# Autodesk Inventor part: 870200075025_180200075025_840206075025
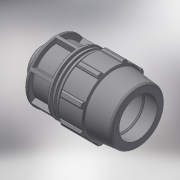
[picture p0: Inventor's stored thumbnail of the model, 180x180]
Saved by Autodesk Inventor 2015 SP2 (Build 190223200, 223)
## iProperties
Created: 2017-02
Part Number: 870200075025_180200075025_840206075025
Material: Generic
Description: PLASSON MALE ADAPTOR 75-2.1/2"
Document SubType Name: Modeling
Designer: KIM
Mass: 964.158 g
Surface Area: 1468.9 cm^2
Volume: 964.158 cm^3
Density: 1 g/cm^3
Appearance: Default
Author: KIM
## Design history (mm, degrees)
derived "87020.ipt"
feature "Solid1::87020.ipt"
tag "TaggingFeature1"
body "Solid1"
other parameters: "d2" = 75, "d4" = 27.42857, "d5" = 48, "d7" = 132, "d8" = 99, "d9" = 27.42857, "d11" = 5.48571, "d12" = 105.6, "d13" = 120 deg, "d14" = 105, "d15" = 6 deg, "d16" = 118.8, "d18" = 3.75, "d19" = 35 deg, "d20" = 17.5 deg, "d21" = 122.76, "d23" = 0, "d25" = 360 deg, "d27" = 2.64, "d34" = 6.6, "d36" = 0, "d42" = 48, "d43" = 3.96, "d46" = 2.25, "d49" = 156, "d51" = 192, "d52" = 29, "d53" = 1.5, "d55" = 360 deg, "d57" = 75.184, "d58" = 52.6288, "d59" = 38.4, "d61" = 116.424, "d62" = 3.52571, "d63" = 3.52571, "d66" = 7.05143, "d_" = 75, "E_" = 132, "H_" = 192, "l_" = 156, "l_2" = 29, "R_" = 75.184, "d60" = 17.62857
